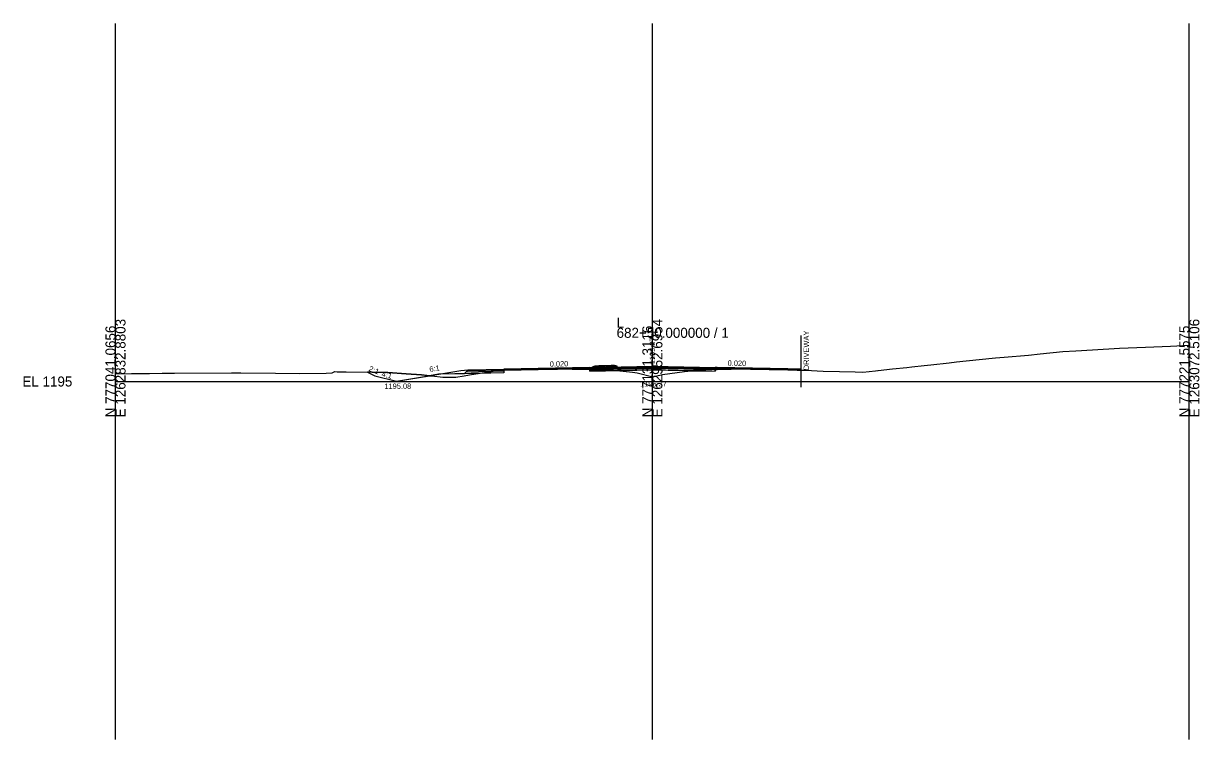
# Model space of a CAD drawing. Extents: x -41 to 1262860, y -100 to 777489.
# Drawn here: x 974.3 to 1302.8, y -100 to 100 of the extents above; entities that cross this region are included whole.
import ezdxf

# ---------------------------------------------------------------- set-up
doc = ezdxf.new("R2010")
doc.units = 0
for name, color, linetype in [('Exist Cross Section Cell', 7, 'Continuous'), ('Exist XS Center Line Elevation Label', 7, 'Continuous'), ('Exist XS Ground Line', 7, 'Continuous'), ('Prop CMT Pvmt Course 1', 7, 'Continuous'), ('Prop CMT Pvmt Surface', 7, 'Continuous'), ('Prop CMT Shear Line', 7, 'Continuous'), ('Prop CMT Shld Paved Course 1', 7, 'Continuous'), ('Prop CMT Shld Paved Course 2', 7, 'Continuous'), ('Prop CMT Shld Paved Course 4', 7, 'Continuous'), ('Prop CMT Subgrade Earthwork', 7, 'Continuous'), ('Prop Conc Curb and Gutter', 7, 'Continuous'), ('Prop Conc Island Cover', 7, 'Continuous'), ('Prop XS Ditch Standard Text', 7, 'Continuous'), ('Prop XS Earthwork Shape', 7, 'Continuous'), ('Prop XS Exc Vertical Line 1', 7, 'Continuous'), ('Prop XS Exc Vertical Line 2', 7, 'Continuous'), ('Prop XS Exc Vertical Line 3', 7, 'Continuous'), ('Prop XS Finish Grade', 7, 'Continuous'), ('Prop XS Hydro Elevations', 7, 'Continuous'), ('Prop XS SE Text', 7, 'Continuous'), ('Prop XS Side Slope Text', 7, 'Continuous'), ('Scratch_Level_4', 7, 'Continuous'), ('Scratch_Level_6', 7, 'Continuous')]:
    doc.layers.add(name, color=color, linetype=linetype)

msp = doc.modelspace()

# ---------------------------------------------------------------- linework, layer by layer
at = {"layer": 'Exist Cross Section Cell'}
for p, q in [((1150, 0), (1150, 15)), ((1000, 0), (1150, 0)), ((1150, 0), (1300, 0))]:
    msp.add_line(p, q, dxfattribs=at)
at = {"layer": 'Exist XS Ground Line'}
msp.add_lwpolyline([(1000, 2.14), (1004.43, 2.23), (1006.86, 2.24), (1009.5, 2.24), (1013.04, 2.32), (1016.5, 2.36), (1032.41, 2.43), (1035.06, 2.43), (1044.67, 2.29), (1051.38, 2.25), (1058.87, 2.37), (1060.5, 2.42), (1061.11, 2.72), (1061.15, 2.75), (1061.91, 2.74), (1064.41, 2.7), (1071.67, 2.62), (1076.11, 2.54), (1081.22, 2.14), (1085.52, 1.84), (1088.35, 1.56), (1091.41, 1.21), (1092.97, 1.2), (1095.1, 1.21), (1097.37, 1.59), (1097.91, 1.69), (1099.46, 1.95), (1103.63, 2.63), (1104.91, 2.81), (1107.25, 3.16), (1108.33, 3.24), (1110.74, 3.39), (1114.91, 3.44), (1123.49, 3.51), (1127.55, 3.45), (1135.37, 3.33), (1136.68, 3.26), (1139.1, 3.15), (1144.48, 2.59), (1145.09, 2.54), (1145.71, 2.39), (1150.08, 1.35), (1150.82, 1.53), (1152.84, 1.98), (1159.01, 2.77), (1160.86, 3.02), (1161.49, 3.1), (1164.91, 3.28), (1165.34, 3.31), (1166.64, 3.33), (1177.38, 3.55), (1188.48, 3.33), (1189.54, 3.31), (1189.95, 3.27), (1190.42, 3.25), (1191.17, 3.21), (1192.81, 3.12), (1197.71, 2.86), (1202.24, 2.82), (1206.67, 2.66), (1208.78, 2.59), (1212.35, 2.97), (1212.94, 3.04), (1213.03, 3.05), (1217.07, 3.51), (1221.09, 3.92), (1222.45, 4.07), (1225.96, 4.44), (1227.79, 4.62), (1232.92, 5.19), (1234.98, 5.51), (1237.64, 5.78), (1245.84, 6.62), (1248.28, 6.8), (1255.03, 7.38), (1258.35, 7.71), (1264.66, 8.35), (1268.29, 8.58), (1272.96, 8.85), (1280.5, 9.27), (1287.78, 9.58), (1294.74, 9.86), (1300, 10.11)], dxfattribs=at)
at = {"layer": 'Prop CMT Pvmt Course 1'}
for p, q in [((1132.5, 3.67), (1150, 4.02)), ((1150, 4.02), (1167.5, 3.67))]:
    msp.add_line(p, q, dxfattribs=at)
for points in [[(1108.5, 3.44), (1108.5, 3.19), (1108.5, 3.19), (1132.5, 3.67), (1132.5, 3.67), (1132.5, 3.92), (1132.5, 3.92), (1132.5, 3.92), (1108.5, 3.44), (1108.5, 3.44), (1108.5, 3.44)], [(1191.5, 3.44), (1191.5, 3.44), (1191.5, 3.44), (1187.88, 3.51), (1187.88, 3.51), (1168.05, 3.91), (1167.97, 3.91), (1167.97, 3.91), (1167.84, 3.91), (1167.84, 3.91), (1167.68, 3.91), (1167.68, 3.91), (1167.68, 3.91), (1167.51, 3.92), (1167.5, 3.92), (1167.5, 3.92), (1167.5, 3.67), (1167.51, 3.67), (1167.68, 3.66), (1167.68, 3.66), (1167.68, 3.66), (1167.84, 3.66), (1167.84, 3.66), (1167.97, 3.66), (1167.97, 3.66), (1168.05, 3.66), (1187.88, 3.26), (1187.88, 3.26), (1191.5, 3.19), (1191.5, 3.19), (1191.5, 3.44)]]:
    msp.add_lwpolyline(points, dxfattribs=at)
at = {"layer": 'Prop CMT Pvmt Surface'}
for p, q in [((1098.5, 3.24), (1108.5, 3.44)), ((1108.5, 3.44), (1132.5, 3.92)), ((1132.5, 3.92), (1150, 4.27)), ((1150, 4.27), (1167.5, 3.92)), ((1167.5, 3.92), (1191.5, 3.44))]:
    msp.add_line(p, q, dxfattribs=at)
at = {"layer": 'Prop CMT Shear Line'}
msp.add_line((1191.5, 12.87), (1191.5, -1.56), dxfattribs=at)
at = {"layer": 'Prop CMT Shld Paved Course 1'}
for p, q in [((1108.5, 3.44), (1108.5, 3.44)), ((1108.5, 3.44), (1108.5, 3.44)), ((1108.5, 3.44), (1108.5, 3.19)), ((1098.24, 2.98), (1098.5, 3.24)), ((1108.5, 3.19), (1098.24, 2.98)), ((1108.5, 3.19), (1108.5, 3.19))]:
    msp.add_line(p, q, dxfattribs=at)
at = {"layer": 'Prop CMT Shld Paved Course 2'}
for p, q in [((1110.74, 3.23), (1114.91, 3.32)), ((1114.91, 3.32), (1110.74, 3.23)), ((1114.91, 3.32), (1123.49, 3.49)), ((1123.49, 3.49), (1114.91, 3.32)), ((1114.91, 3.32), (1114.91, 3.32)), ((1114.91, 3.32), (1114.91, 3.32)), ((1123.49, 3.49), (1127.55, 3.57)), ((1124.21, 3.5), (1123.49, 3.49)), ((1123.49, 3.49), (1123.49, 3.49)), ((1127.55, 3.45), (1124.21, 3.5)), ((1124.21, 3.5), (1124.21, 3.5)), ((1124.21, 3.5), (1124.21, 3.5)), ((1127.55, 3.57), (1132.5, 3.67)), ((1127.55, 3.57), (1127.55, 3.57)), ((1127.55, 3.57), (1127.55, 3.57)), ((1132.5, 3.37), (1127.55, 3.45)), ((1127.55, 3.45), (1127.55, 3.45)), ((1127.55, 3.45), (1127.55, 3.45)), ((1132.5, 3.33), (1150, 3.68)), ((1132.5, 3.67), (1132.5, 3.67)), ((1132.5, 3.67), (1132.5, 3.67)), ((1132.5, 3.67), (1132.5, 3.37)), ((1132.5, 3.37), (1132.5, 3.33)), ((1132.5, 3.37), (1132.5, 3.37)), ((1150, 3.68), (1167.5, 3.33)), ((1167.5, 3.35), (1167.5, 3.33)), ((1097.9, 2.64), (1098.24, 2.98)), ((1108.5, 2.85), (1097.9, 2.64)), ((1108.5, 3.19), (1110.74, 3.23)), ((1110.74, 3.23), (1108.5, 3.19)), ((1108.5, 3.19), (1108.5, 3.19)), ((1108.5, 3.19), (1108.5, 3.19)), ((1108.5, 3.19), (1108.5, 2.85)), ((1108.5, 2.85), (1108.5, 2.85)), ((1110.74, 3.23), (1110.74, 3.23)), ((1110.74, 3.23), (1110.74, 3.23)), ((1110.74, 3.23), (1110.74, 3.23)), ((1110.74, 3.23), (1110.74, 3.23))]:
    msp.add_line(p, q, dxfattribs=at)
for points in [[(1191.5, 3.19), (1191.17, 3.19), (1191.17, 3.19), (1190.42, 3.21), (1190.42, 3.21), (1189.95, 3.22), (1189.95, 3.22), (1189.54, 3.23), (1188.48, 3.25), (1188.48, 3.25), (1187.88, 3.26), (1187.88, 3.26), (1177.38, 3.47), (1177.38, 3.47), (1177.38, 3.47), (1168.05, 3.66), (1168.05, 3.66), (1167.97, 3.66), (1167.97, 3.66), (1167.84, 3.66), (1167.84, 3.66), (1167.68, 3.66), (1167.68, 3.66), (1167.5, 3.67)], [(1167.5, 3.67), (1167.5, 3.67), (1167.5, 3.67), (1167.5, 3.35), (1167.51, 3.35), (1167.68, 3.35), (1167.68, 3.35), (1167.68, 3.35), (1167.84, 3.35), (1167.84, 3.35), (1167.97, 3.36), (1167.97, 3.36), (1168.05, 3.36), (1175.34, 3.51), (1175.34, 3.51), (1177.38, 3.47), (1177.38, 3.47), (1177.38, 3.47), (1187.88, 3.26), (1187.88, 3.26), (1188.48, 3.25), (1188.48, 3.25), (1189.54, 3.23), (1189.95, 3.22), (1189.95, 3.22), (1190.42, 3.21), (1190.42, 3.21), (1191.17, 3.19), (1191.17, 3.19), (1191.5, 3.19), (1191.5, 3.19)]]:
    msp.add_lwpolyline(points, dxfattribs=at)
at = {"layer": 'Prop CMT Shld Paved Course 4'}
for p, q in [((1132.5, 3.33), (1132.5, 2.88)), ((1167.5, 3.33), (1167.5, 2.88)), ((1097.44, 2.17), (1097.9, 2.64)), ((1108.5, 2.4), (1097.44, 2.17)), ((1108.5, 2.85), (1108.5, 2.85)), ((1108.5, 2.85), (1108.5, 2.85)), ((1108.5, 2.85), (1108.5, 2.4)), ((1132.5, 2.88), (1150, 3.23)), ((1150, 3.23), (1167.5, 2.88))]:
    msp.add_line(p, q, dxfattribs=at)
at = {"layer": 'Prop CMT Subgrade Earthwork'}
for p, q in [((1132.5, 3.37), (1132.5, 2.88)), ((1167.5, 2.88), (1167.5, 3.35)), ((1108.5, 2.4), (1090.22, 2.03)), ((1108.5, 3.25), (1108.5, 2.4)), ((1132.5, 2.88), (1150, 3.23)), ((1150, 3.23), (1167.5, 2.88))]:
    msp.add_line(p, q, dxfattribs=at)
at = {"layer": 'Prop Conc Curb and Gutter'}
for p, q in [((1133.25, 3.93), (1133.26, 4.1)), ((1133.25, 3.93), (1133.25, 3.93)), ((1133.25, 3.93), (1133.25, 3.81)), ((1135.01, 3.93), (1133.25, 3.93)), ((1133.25, 3.93), (1133.25, 3.93)), ((1133.25, 3.81), (1133.25, 3.81)), ((1133.25, 3.81), (1135.01, 3.81)), ((1133.26, 4.1), (1134.01, 4.35)), ((1133.26, 4.1), (1133.26, 4.1)), ((1134.01, 4.35), (1135.01, 4.37)), ((1134.01, 4.35), (1134.01, 4.35)), ((1135.01, 4.37), (1135.01, 3.93)), ((1135.01, 3.81), (1135.01, 3.93)), ((1135.01, 3.93), (1135.01, 3.93)), ((1135.01, 3.81), (1135.01, 3.81)), ((1135.01, 3.81), (1135.01, 3.81)), ((1139.44, 4.49), (1138.44, 4.51)), ((1138.44, 4.51), (1138.44, 4.07)), ((1140.2, 4.07), (1138.44, 4.07)), ((1138.44, 4.07), (1138.44, 3.95)), ((1138.44, 4.07), (1138.44, 4.07)), ((1138.44, 3.95), (1138.44, 3.95)), ((1138.44, 3.95), (1140.2, 3.95)), ((1140.19, 4.24), (1139.44, 4.49)), ((1139.44, 4.49), (1139.44, 4.49)), ((1140.2, 4.07), (1140.19, 4.24)), ((1140.19, 4.24), (1140.19, 4.24)), ((1140.2, 3.95), (1140.2, 4.07)), ((1140.2, 4.07), (1140.2, 4.07)), ((1140.2, 4.07), (1140.2, 4.07)), ((1140.2, 3.95), (1140.2, 3.95)), ((1140.2, 3.95), (1140.2, 3.95))]:
    msp.add_line(p, q, dxfattribs=at)
at = {"layer": 'Prop Conc Island Cover'}
for p, q in [((1138.44, 4.51), (1135.01, 4.37)), ((1135.01, 4.37), (1135.01, 4.12)), ((1138.44, 4.26), (1135.01, 4.12)), ((1138.44, 4.26), (1138.44, 4.51)), ((1138.44, 4.51), (1138.44, 4.51)), ((1138.44, 4.26), (1138.44, 4.26))]:
    msp.add_line(p, q, dxfattribs=at)
at = {"layer": 'Prop XS Earthwork Shape'}
for points in [[(1136.68, 3.26), (1139.1, 3.15), (1140.22, 3.03), (1132.5, 2.88), (1132.5, 3.37), (1135.37, 3.33)], [(1160.79, 3.01), (1167.5, 2.88), (1167.5, 3.35), (1166.64, 3.33), (1165.34, 3.31), (1164.91, 3.28), (1161.49, 3.1), (1160.86, 3.02)], [(1078.5, 0.08), (1087.76, 1.62), (1085.52, 1.84), (1081.22, 2.14), (1076.11, 2.54), (1071.67, 2.62), (1070.38, 2.64), (1072.5, 1.58)], [(1097.44, 2.17), (1090.22, 2.03), (1087.76, 1.62), (1088.35, 1.56), (1091.41, 1.21), (1092.97, 1.2), (1095.1, 1.21), (1097.37, 1.59), (1097.91, 1.69), (1099.46, 1.95), (1101.29, 2.25)], [(1103.63, 2.63), (1104.91, 2.81), (1107.25, 3.16), (1108.33, 3.24), (1108.5, 3.25), (1108.5, 2.4), (1101.29, 2.25)], [(1140.22, 3.03), (1144.48, 2.59), (1145.09, 2.54), (1145.71, 2.39), (1150.08, 1.35), (1150.82, 1.53), (1152.84, 1.98), (1159.01, 2.77), (1160.79, 3.01), (1150, 3.23)]]:
    msp.add_lwpolyline(points, close=True, dxfattribs=at)
at = {"layer": 'Prop XS Exc Vertical Line 1'}
msp.add_line((1000, -100), (1000, 100), dxfattribs=at)
at = {"layer": 'Prop XS Exc Vertical Line 2'}
msp.add_line((1150, -100), (1150, 100), dxfattribs=at)
at = {"layer": 'Prop XS Exc Vertical Line 3'}
msp.add_line((1300, -100), (1300, 100), dxfattribs=at)
at = {"layer": 'Prop XS Finish Grade'}
for p, q in [((1070.38, 2.64), (1072.5, 1.58)), ((1072.5, 1.58), (1078.5, 0.08)), ((1078.5, 0.08), (1096.5, 3.08)), ((1096.5, 3.08), (1098.5, 3.24)), ((1097.44, 2.17), (1098.5, 3.24))]:
    msp.add_line(p, q, dxfattribs=at)
at = {"layer": 'Scratch_Level_4'}
msp.add_line((1300, -100), (1300, 100), dxfattribs=at)
at = {"layer": 'Scratch_Level_6'}
msp.add_line((1000, -100), (1000, 100), dxfattribs=at)

# ---------------------------------------------------------------- texts
at = {"layer": 'Exist Cross Section Cell'}
for s, p in [('E 1262832.8803', (1002.8, -10)), ('E 1262952.6954', (1152.8, -10)), ('E 1263072.5106', (1302.8, -10)), ('N 777041.0656', (1000, -10)), ('N 777131.3116', (1150, -10)), ('N 777221.5575', (1300, -10))]:
    msp.add_text(s, height=2.8, rotation=90, dxfattribs=at).set_placement(p)
for s, p in [('L', (1140, 15)), ('682+50.000000 / 1', (1140, 12.2)), ('EL 1195', (974, -1.4))]:
    msp.add_text(s, height=2.8, dxfattribs=at).set_placement(p)
at = {"layer": 'Exist XS Center Line Elevation Label'}
msp.add_text('1196.37', height=1.5, dxfattribs=at).set_placement((1146.54, -1.38))
at = {"layer": 'Prop XS Ditch Standard Text'}
msp.add_text('1195.08', height=1.5, dxfattribs=at).set_placement((1075.13, -2.06))
at = {"layer": 'Prop XS Hydro Elevations'}
for s, p in [('DRIVEWAY', (1193.73, 3.16)), ('1199.27', (1150.75, 4.82))]:
    msp.add_text(s, height=1.5, rotation=90, dxfattribs=at).set_placement(p)
at = {"layer": 'Prop XS SE Text'}
for rotation, p in [(1.1458, (1121.33, 4.13)), (358.8542, (1171.01, 4.41))]:
    msp.add_text('0.020', height=1.5, rotation=rotation, dxfattribs=at).set_placement(p)
at = {"layer": 'Prop XS Side Slope Text'}
for s, rotation, p in [('2:1', 338.2726, (1070.62, 3.02)), ('6:1', 9.4623, (1087.83, 2.64)), ('4:1', 345.9638, (1074.25, 1.45))]:
    msp.add_text(s, height=1.5, rotation=rotation, dxfattribs=at).set_placement(p)

doc.saveas('drawing.dxf')
